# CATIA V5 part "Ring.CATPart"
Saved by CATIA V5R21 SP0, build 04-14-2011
Part number: Part1.1
Bounding box of the stored display mesh (mm): x -5 to 5, y -15 to 15, z -15 to 15
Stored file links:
  D:\CATIA V5R21 E-RESOURCES\CATIA-V5R21\catia-v5r21-prt\c12-catia-v5r20-prt\c12-catia-v5-r20-figr-12-12\cat_v5r21_Ring.CATPart
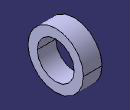
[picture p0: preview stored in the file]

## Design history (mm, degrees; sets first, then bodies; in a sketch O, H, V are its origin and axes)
Body1 (main body)
  Sketch1 on yz-plane, origin (0, 0, 0), H (0, 1, 0), V (0, 0, 1)
    circle A1 centre (0, 0) radius 15
    circle A2 centre (0, 0) radius 10
    radius A1 = 15
    radius A2 = 10
  Pad1: profile Sketch1, direction (1, 0, 0), length 5, mirrored extent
